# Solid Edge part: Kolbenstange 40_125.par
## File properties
Username: ahadarics
Dokumentum tartalom típus: 0
Author: ahadarics
Last saved by: ahadarics
Revision: 82
Sűrűség: 0,000 kg/m^3
Pontosság: 0,990
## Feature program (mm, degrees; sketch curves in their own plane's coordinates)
base feature "unnamed BaseFeature 1"
thread "unnamed Thread 1"
chamfer "Letörés_1"  SetBackValue2 = 20 deg
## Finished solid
Body 1: solid body, 21 faces, 32 edges, 14 vertices.
  Faces by surface: plane 8, cylinder 5, cone 4, torus 4
  Edges by curve: circle 17, line 9, curve on surface 4, ellipse 2
Bounding box of the edges (mm; curved faces can reach further): 40.000 x 40.000 x 253.000, from (-20, -20, -78) to (20, 20, 175).
Cylindrical faces by radius (mm): R5 x1, R6 x1, R7.75 x1, R8 x1, R20 x1
Conical faces (half-angle, radius in mm at the cone's reference point): 20 deg R6 x1, 30 deg R7.875 x1, 45 deg R19.6 x1, 60 deg R5.5 x1
Toroidal faces (ring radius, tube radius in mm): R5.4 r0.4 x2, R6.55 r1.2 x2
Planar faces by outward normal: +x 1, +z 3, -x 1, -z 1, oblique 2
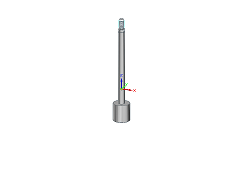
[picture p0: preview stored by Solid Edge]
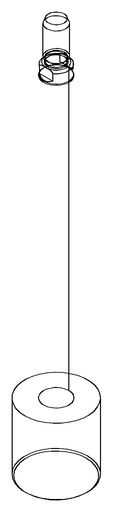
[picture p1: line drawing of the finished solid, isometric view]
